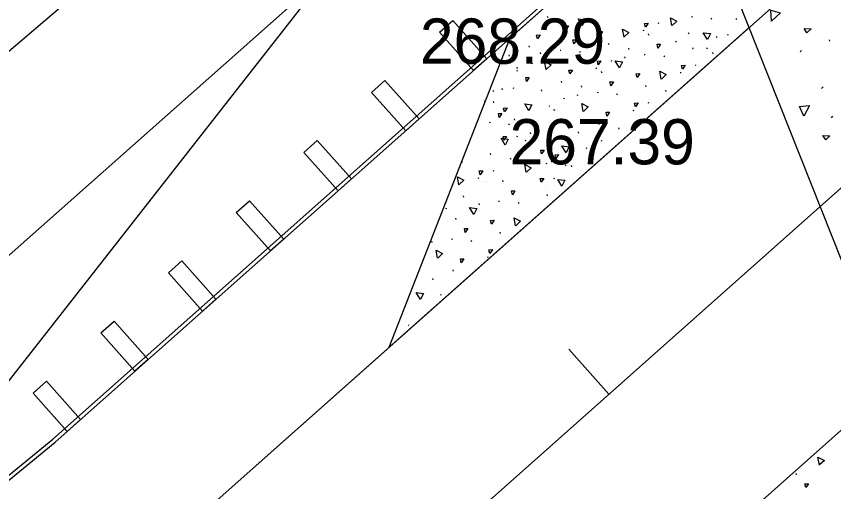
# Model space of a CAD drawing. Extents: x 49683 to 58852, y 49525 to 54803.
# Drawn here: x 55220.9 to 55275.1, y 53030.3 to 53061.8 of the extents above; entities that cross this region are included whole.
import ezdxf

# ---------------------------------------------------------------- set-up
doc = ezdxf.new("R2010")
doc.units = 0
for name, color, linetype in [('Level 13', 7, 'Continuous'), ('Level 15', 7, 'Continuous'), ('Level 18', 7, 'Continuous'), ('Level 19', 7, 'Continuous'), ('Level 20', 7, 'Continuous'), ('Level 27', 7, 'Continuous'), ('Level 3', 7, 'Continuous'), ('Level 32', 7, 'Continuous'), ('Level 8', 7, 'Continuous')]:
    doc.layers.add(name, color=color, linetype=linetype)

msp = doc.modelspace()

# ---------------------------------------------------------------- linework, layer by layer
at = {"layer": 'Level 13'}
msp.add_line((55279.532, 53069.998), (53969.027, 51905.114), dxfattribs=at)
at = {"layer": 'Level 15'}
for p, q in [((55253.595, 53060.324), (55265.526, 53070.929)), ((55282.788, 53027.404), (55265.526, 53070.929)), ((55245.587, 53039.827), (55269.449, 53061.037)), ((55253.595, 53060.324), (55245.587, 53039.827)), ((55274.798, 53060.124), (55274.775, 53060.221)), ((55272.925, 53059.521), (55272.83, 53059.423)), ((55274.347, 53057.099), (55274.252, 53057.001)), ((55274.983, 53055.155), (55274.888, 53055.057)), ((55255.003, 53016.086), (55278.865, 53037.296))]:
    msp.add_line(p, q, dxfattribs=at)
for points in [[(55271.531, 53062.006), (55270.937, 53061.469), (55270.886, 53062.181), (55271.518, 53062.01)], [(55273.553, 53060.961), (55273.278, 53060.692), (55273.088, 53060.983), (55273.553, 53060.961)], [(55273.446, 53055.867), (55273.071, 53055.16), (55272.78, 53055.812), (55273.432, 53055.867)], [(55274.802, 53053.855), (55274.527, 53053.586), (55274.338, 53053.876), (55274.802, 53053.855)]]:
    msp.add_lwpolyline(points, dxfattribs=at)
at = {"layer": 'Level 18'}
msp.add_line((55193.446, 53036.534), (55231.532, 53068.947), dxfattribs=at)
at = {"layer": 'Level 19'}
for p, q in [((54181.768, 52078.16), (56150.851, 53828.445)), ((55260.168, 53036.732), (55257.51, 53039.721))]:
    msp.add_line(p, q, dxfattribs=at)
at = {"layer": 'Level 20'}
for p, q in [((54173.795, 52087.129), (55269.449, 53061.037)), ((54189.74, 52069.191), (55278.865, 53037.296))]:
    msp.add_line(p, q, dxfattribs=at)
at = {"layer": 'Level 27'}
for p, q in [((55223.318, 53033.746), (55265.359, 53071.116)), ((55223.484, 53033.559), (55265.526, 53070.929)), ((55248.93, 53060.727), (55249.814, 53061.512)), ((55249.814, 53061.512), (55252.072, 53058.971)), ((55251.189, 53058.186), (55248.93, 53060.727)), ((55252.072, 53058.971), (55251.189, 53058.186)), ((55244.446, 53056.741), (55245.329, 53057.526)), ((55245.329, 53057.526), (55247.588, 53054.984)), ((55246.704, 53054.199), (55244.446, 53056.741)), ((55247.588, 53054.984), (55246.704, 53054.199)), ((55239.961, 53052.755), (55240.845, 53053.54)), ((55240.845, 53053.54), (55243.103, 53050.998)), ((55242.22, 53050.213), (55239.961, 53052.755)), ((55243.103, 53050.998), (55242.22, 53050.213)), ((55235.476, 53048.769), (55236.36, 53049.554)), ((55236.36, 53049.554), (55238.618, 53047.013)), ((55237.735, 53046.228), (55235.476, 53048.769)), ((55238.618, 53047.013), (55237.735, 53046.228)), ((55230.991, 53044.784), (55231.875, 53045.569)), ((55231.875, 53045.569), (55234.133, 53043.027)), ((55233.25, 53042.242), (55230.991, 53044.784)), ((55234.133, 53043.027), (55233.25, 53042.242)), ((55226.506, 53040.798), (55227.39, 53041.583)), ((55227.39, 53041.583), (55229.648, 53039.042)), ((55228.765, 53038.257), (55226.506, 53040.798)), ((55229.648, 53039.042), (55228.765, 53038.257)), ((55222.023, 53036.81), (55222.907, 53037.595)), ((55222.907, 53037.595), (55225.165, 53035.054)), ((55224.282, 53034.268), (55222.023, 53036.81)), ((55225.165, 53035.054), (55224.282, 53034.268)), ((55203.976, 53017.891), (55223.325, 53033.752)), ((55204.134, 53017.697), (55223.484, 53033.559))]:
    msp.add_line(p, q, dxfattribs=at)
at = {"layer": 'Level 3'}
msp.add_line((55065.24, 52908.355), (55241.707, 53064.82), dxfattribs=at)
at = {"layer": 'Level 8'}
for p, q in [((55179.239, 52985.046), (55241.707, 53064.82)), ((55256.072, 53061.772), (55256.131, 53061.713)), ((55263.408, 53061.345), (55263.472, 53061.325)), ((55265.629, 53061.761), (55265.693, 53061.74)), ((55266.914, 53061.652), (55266.973, 53061.593)), ((55268.566, 53061.633), (55268.626, 53061.574)), ((55257.16, 53060.687), (55257.223, 53060.667)), ((55257.23, 53060.822), (55257.207, 53060.911)), ((55258.15, 53061.178), (55258.213, 53061.158)), ((55262.419, 53060.854), (55262.482, 53060.834)), ((55265.411, 53060.682), (55265.47, 53060.623)), ((55257.592, 53060.359), (55257.592, 53060.359)), ((55257.722, 53060.463), (55257.722, 53060.463)), ((55262.813, 53060.536), (55262.789, 53060.624)), ((55262.851, 53060.526), (55262.851, 53060.526)), ((55262.981, 53060.63), (55262.981, 53060.63)), ((55267.272, 53060.439), (55267.331, 53060.38)), ((55268.002, 53060.568), (55268.065, 53060.547)), ((55254.911, 53059.728), (55254.888, 53059.816)), ((55260.17, 53059.895), (55260.147, 53059.983)), ((55261.498, 53059.583), (55261.475, 53059.671)), ((55264.582, 53060.135), (55264.641, 53060.076)), ((55265.753, 53059.608), (55265.73, 53059.696)), ((55266.625, 53059.69), (55266.684, 53059.631)), ((55253.577, 53059.145), (55253.554, 53059.233)), ((55255.652, 53059.286), (55255.629, 53059.374)), ((55256.239, 53059.416), (55256.216, 53059.504)), ((55256.924, 53059.547), (55256.988, 53059.527)), ((55258.209, 53059.439), (55258.268, 53059.38)), ((55261.234, 53059), (55261.211, 53059.088)), ((55262.507, 53059.26), (55262.57, 53059.24)), ((55263.792, 53059.152), (55263.851, 53059.093)), ((55267.081, 53059.297), (55267.058, 53059.385)), ((55255.027, 53058.678), (55255.091, 53058.658)), ((55260.286, 53058.845), (55260.35, 53058.825)), ((55265.869, 53058.558), (55265.932, 53058.538)), ((55254.038, 53058.187), (55254.101, 53058.167)), ((55254.108, 53058.322), (55254.084, 53058.41)), ((55259.297, 53058.354), (55259.36, 53058.334)), ((55259.69, 53058.036), (55259.667, 53058.124)), ((55259.729, 53058.026), (55259.729, 53058.026)), ((55259.859, 53058.13), (55259.859, 53058.13)), ((55264.879, 53058.067), (55264.943, 53058.047)), ((55254.47, 53057.859), (55254.47, 53057.859)), ((55254.6, 53057.963), (55254.6, 53057.963)), ((55257.048, 53057.394), (55257.025, 53057.483)), ((55265.311, 53057.739), (55265.311, 53057.739)), ((55265.442, 53057.843), (55265.442, 53057.843)), ((55253.117, 53056.916), (55253.094, 53057.004)), ((55253.802, 53057.047), (55253.866, 53057.026)), ((55255.714, 53056.812), (55255.69, 53056.9)), ((55258.376, 53057.083), (55258.353, 53057.171)), ((55262.631, 53057.108), (55262.608, 53057.196)), ((55252.529, 53056.786), (55252.506, 53056.874)), ((55258.112, 53056.499), (55258.089, 53056.587)), ((55259.385, 53056.76), (55259.448, 53056.74)), ((55260.669, 53056.652), (55260.729, 53056.593)), ((55263.958, 53056.796), (55263.935, 53056.884)), ((55251.905, 53056.178), (55251.969, 53056.157)), ((55252.532, 53056.036), (55252.509, 53056.125)), ((55256.174, 53055.854), (55256.238, 53055.833)), ((55257.164, 53056.345), (55257.227, 53056.324)), ((55262.747, 53056.058), (55262.81, 53056.038)), ((55256.568, 53055.535), (55256.545, 53055.624)), ((55256.607, 53055.525), (55256.607, 53055.525)), ((55256.737, 53055.63), (55256.737, 53055.63)), ((55261.757, 53055.567), (55261.821, 53055.547)), ((55262.319, 53055.343), (55262.319, 53055.343)), ((55252.226, 53054.761), (55252.29, 53054.741)), ((55253.926, 53054.894), (55253.903, 53054.982)), ((55262.189, 53055.239), (55262.189, 53055.239)), ((55253.511, 53054.653), (55253.57, 53054.593)), ((55255.253, 53054.583), (55255.23, 53054.671)), ((55256.262, 53054.26), (55256.326, 53054.24)), ((55259.508, 53054.607), (55259.485, 53054.696)), ((55260.836, 53054.296), (55260.813, 53054.384)), ((55254.042, 53053.844), (55254.105, 53053.824)), ((55254.99, 53053.999), (55254.967, 53054.087)), ((55258.174, 53054.025), (55258.151, 53054.113)), ((55254.599, 53053.568), (55254.662, 53053.548)), ((55256.287, 53053.314), (55256.264, 53053.403)), ((55259.624, 53053.558), (55259.688, 53053.537)), ((55252.35, 53052.608), (55252.327, 53052.697)), ((55253.484, 53053.025), (55253.484, 53053.025)), ((55258.635, 53053.067), (55258.698, 53053.047)), ((55259.067, 53052.739), (55259.067, 53052.739)), ((55259.197, 53052.843), (55259.197, 53052.843)), ((55250.389, 53052.152), (55250.448, 53052.093)), ((55253.678, 53052.297), (55253.655, 53052.385)), ((55255.982, 53052.039), (55256.045, 53052.019)), ((55256.386, 53052.107), (55256.363, 53052.195)), ((55252.466, 53051.558), (55252.53, 53051.538)), ((55257.266, 53051.931), (55257.326, 53051.871)), ((55257.714, 53051.796), (55257.691, 53051.884)), ((55251.476, 53051.068), (55251.54, 53051.047)), ((55256.502, 53051.057), (55256.566, 53051.037)), ((55251.909, 53050.739), (55251.909, 53050.739)), ((55252.039, 53050.844), (55252.039, 53050.844)), ((55253.165, 53050.814), (55253.142, 53050.902)), ((55250.556, 53049.797), (55250.532, 53049.885)), ((55255.945, 53050.238), (55255.945, 53050.238)), ((55256.106, 53049.886), (55256.082, 53049.974)), ((55251.587, 53049.278), (55251.564, 53049.366)), ((55252.859, 53049.538), (55252.923, 53049.518)), ((55254.144, 53049.43), (55254.203, 53049.371)), ((55249.344, 53049.058), (55249.407, 53049.038)), ((55248.916, 53048.343), (55248.916, 53048.343)), ((55250.043, 53048.314), (55250.02, 53048.402)), ((55252.983, 53047.386), (55252.96, 53047.474)), ((55248.464, 53046.778), (55248.441, 53046.866)), ((55249.737, 53047.038), (55249.801, 53047.018)), ((55251.022, 53046.93), (55251.081, 53046.871)), ((55252.109, 53045.845), (55252.173, 53045.825)), ((55249.861, 53044.886), (55249.838, 53044.974)), ((55248.526, 53044.303), (55248.503, 53044.391)), ((55248.987, 53043.345), (55249.051, 53043.325)), ((55246.855, 53041.336), (55246.918, 53041.315)), ((55272.601, 53031.393), (55272.577, 53031.481))]:
    msp.add_line(p, q, dxfattribs=at)
for points in [[(55258.394, 53061.151), (55258.121, 53061.61), (55258.593, 53061.55), (55258.399, 53061.159)], [(55262.58, 53061.066), (55262.522, 53061.315), (55262.753, 53061.323), (55262.58, 53061.066)], [(55264.336, 53061.163), (55264.236, 53061.687), (55264.659, 53061.469), (55264.343, 53061.169)], [(55257.321, 53060.898), (55257.263, 53061.148), (55257.494, 53061.156), (55257.321, 53060.898)], [(55259.575, 53060.514), (55259.517, 53060.764), (55259.748, 53060.771), (55259.575, 53060.514)], [(55261.171, 53060.404), (55261.071, 53060.928), (55261.494, 53060.71), (55261.178, 53060.41)], [(55266.691, 53060.237), (55266.418, 53060.695), (55266.89, 53060.635), (55266.696, 53060.245)], [(55255.435, 53060.292), (55255.377, 53060.542), (55255.609, 53060.55), (55255.435, 53060.292)], [(55257.833, 53059.966), (55257.775, 53060.216), (55258.006, 53060.223), (55257.833, 53059.966)], [(55263.415, 53059.68), (55263.357, 53059.929), (55263.589, 53059.937), (55263.415, 53059.68)], [(55256.006, 53058.256), (55255.906, 53058.78), (55256.329, 53058.562), (55256.013, 53058.261)], [(55259.457, 53058.565), (55259.399, 53058.815), (55259.631, 53058.822), (55259.457, 53058.565)], [(55260.854, 53058.364), (55260.581, 53058.823), (55261.054, 53058.763), (55260.859, 53058.372)], [(55265.04, 53058.279), (55264.982, 53058.528), (55265.213, 53058.536), (55265.04, 53058.279)], [(55257.572, 53057.959), (55257.514, 53058.209), (55257.745, 53058.216), (55257.572, 53057.959)], [(55262.035, 53057.727), (55261.977, 53057.977), (55262.208, 53057.985), (55262.035, 53057.727)], [(55263.631, 53057.617), (55263.531, 53058.141), (55263.955, 53057.923), (55263.638, 53057.623)], [(55254.71, 53057.466), (55254.652, 53057.716), (55254.884, 53057.723), (55254.71, 53057.466)], [(55260.293, 53057.179), (55260.235, 53057.429), (55260.466, 53057.437), (55260.293, 53057.179)], [(55254.864, 53055.523), (55254.591, 53055.981), (55255.063, 53055.921), (55254.869, 53055.531)], [(55258.466, 53055.469), (55258.366, 53055.993), (55258.789, 53055.775), (55258.473, 53055.475)], [(55261.918, 53055.778), (55261.86, 53056.028), (55262.091, 53056.036), (55261.918, 53055.778)], [(55252.898, 53055.081), (55252.84, 53055.331), (55253.071, 53055.338), (55252.898, 53055.081)], [(55253.248, 53055.448), (55253.19, 53055.697), (55253.421, 53055.705), (55253.248, 53055.448)], [(55260.032, 53055.172), (55259.975, 53055.422), (55260.206, 53055.43), (55260.032, 53055.172)], [(55257.171, 53054.679), (55257.113, 53054.929), (55257.344, 53054.936), (55257.171, 53054.679)], [(55253.288, 53053.237), (55253.015, 53053.696), (55253.488, 53053.636), (55253.293, 53053.245)], [(55253.213, 53053.565), (55253.155, 53053.815), (55253.386, 53053.822), (55253.213, 53053.565)], [(55257.324, 53052.736), (55257.051, 53053.194), (55257.524, 53053.134), (55257.329, 53052.744)], [(55255.708, 53052.661), (55255.65, 53052.911), (55255.881, 53052.918), (55255.708, 53052.661)], [(55256.654, 53052.359), (55256.596, 53052.609), (55256.827, 53052.616), (55256.654, 53052.359)], [(55251.637, 53051.279), (55251.579, 53051.529), (55251.81, 53051.536), (55251.637, 53051.279)], [(55254.688, 53051.441), (55254.588, 53051.966), (55255.012, 53051.748), (55254.695, 53051.447)], [(55250.228, 53050.617), (55250.128, 53051.141), (55250.552, 53050.923), (55250.235, 53050.623)], [(55255.673, 53050.778), (55255.615, 53051.028), (55255.846, 53051.035), (55255.673, 53050.778)], [(55257.044, 53050.515), (55256.771, 53050.974), (55257.243, 53050.914), (55257.049, 53050.523)], [(55253.768, 53049.958), (55253.71, 53050.208), (55253.941, 53050.215), (55253.768, 53049.958)], [(55251.207, 53048.642), (55250.934, 53049.101), (55251.406, 53049.041), (55251.212, 53048.65)], [(55252.388, 53048.006), (55252.33, 53048.255), (55252.561, 53048.263), (55252.388, 53048.006)], [(55253.984, 53047.895), (55253.884, 53048.419), (55254.307, 53048.201), (55253.991, 53047.901)], [(55250.646, 53047.458), (55250.588, 53047.707), (55250.819, 53047.715), (55250.646, 53047.458)], [(55248.818, 53045.747), (55248.719, 53046.271), (55249.142, 53046.053), (55248.826, 53045.753)], [(55252.27, 53046.057), (55252.212, 53046.306), (55252.443, 53046.314), (55252.27, 53046.057)], [(55250.385, 53045.451), (55250.327, 53045.7), (55250.558, 53045.708), (55250.385, 53045.451)], [(55247.677, 53043.014), (55247.404, 53043.473), (55247.876, 53043.413), (55247.682, 53043.022)], [(55274.118, 53032.034), (55274.014, 53032.557), (55274.439, 53032.343), (55274.125, 53032.04)], [(55273.211, 53030.542), (55273.151, 53030.792), (55273.382, 53030.801), (55273.211, 53030.542)]]:
    msp.add_lwpolyline(points, dxfattribs=at)

# ---------------------------------------------------------------- texts
at = {"layer": 'Level 32'}
for s, p in [('268.29', (55247.641, 53058.637)), ('267.39', (55253.584, 53051.967))]:
    msp.add_text(s, height=3, dxfattribs=at).set_placement(p)

doc.saveas('drawing.dxf')
